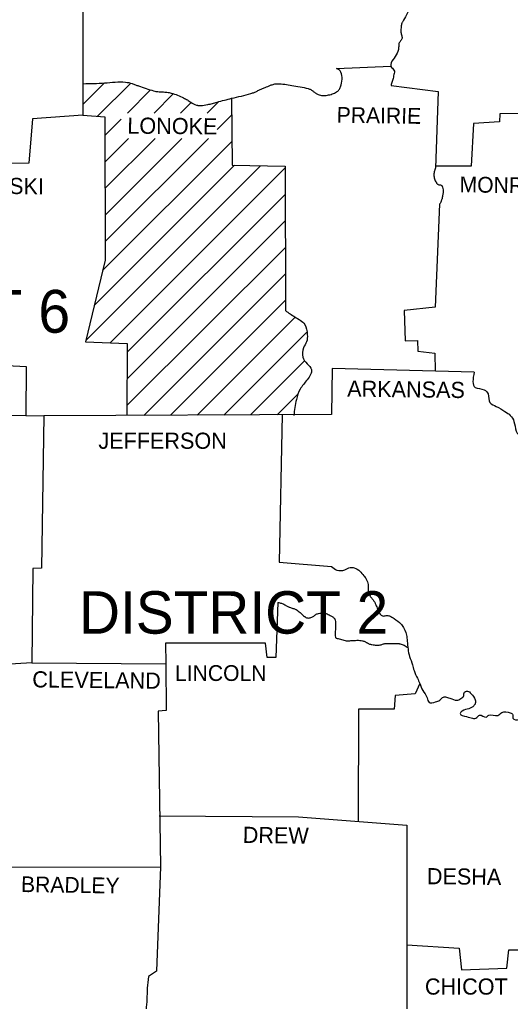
# Model space of a CAD drawing. Extents: x 1373878 to 1386598, y 1168333 to 1170533.
# Drawn here: x 1376588.9 to 1376719.5, y 1169816.7 to 1170078.1 of the extents above; entities that cross this region are included whole.
import ezdxf

# ---------------------------------------------------------------- set-up
doc = ezdxf.new("R2010")
doc.units = 0
for name, color, linetype in [('1', 7, 'Continuous'), ('Default', 7, 'Continuous'), ('R_Draft', 7, 'Continuous')]:
    doc.layers.add(name, color=color, linetype=linetype)

msp = doc.modelspace()

# ---------------------------------------------------------------- linework, layer by layer
at = {"layer": '1'}
for points in [[(1376599.19, 1170281.6), (1376599.39, 1170257.2), (1376597.69, 1170257.1), (1376597.99, 1170232.2), (1376590.99, 1170231.2), (1376591.59, 1170224.5), (1376593.99, 1170221.4), (1376593.79, 1170213.5), (1376580.19, 1170213), (1376579.69, 1170200.8), (1376567.29, 1170200.4), (1376566.69, 1170185.61), (1376567.39, 1170184.41), (1376567.69, 1170160.81), (1376589.09, 1170159.41), (1376588.79, 1170106.71), (1376605.79, 1170106.21), (1376605.79, 1170052.61), (1376592.39, 1170051.61), (1376591.39, 1170039.81), (1376568.89, 1170039.71)], [(1376673.29, 1170065.01), (1376687.68, 1170065.7)], [(1376687.79, 1170060.51), (1376700.29, 1170058.91), (1376699.59, 1170038.51)], [(1376700.69, 1170028.91), (1376699.49, 1170001.51), (1376691.29, 1170000.61), (1376691.49, 1169992.51), (1376694.79, 1169992.61), (1376694.89, 1169989.81), (1376699.39, 1169989.31), (1376699.54, 1169984.48)], [(1376709.89, 1169984.21), (1376672.09, 1169985.21), (1376671.89, 1169972.91), (1376595.39, 1169972.61)], [(1376537.79, 1169959.41), (1376543.39, 1169960.21), (1376543.79, 1169963.61), (1376547.09, 1169964.21), (1376547.29, 1169966.21), (1376570.59, 1169966.91), (1376571.49, 1169973.01), (1376595.39, 1169972.61)], [(1376592.19, 1169906.81), (1376577.57, 1169905.91)], [(1376592.19, 1169906.81), (1376627.82, 1169906.61)], [(1376627.82, 1169906.61), (1376627.89, 1169894.11), (1376625.79, 1169894.01), (1376626.39, 1169852.51)], [(1376626.39, 1169852.51), (1376625.39, 1169824.71), (1376623.19, 1169823.31)]]:
    msp.add_lwpolyline(points, dxfattribs=at)
for points in [[(1376700.49, 1170119.51), (1376700.43, 1170118.68), (1376700.36, 1170117.85), (1376700.22, 1170117.02), (1376700.12, 1170116.61), (1376700.06, 1170116.41), (1376699.99, 1170116.21), (1376699.67, 1170115.84), (1376699.16, 1170115.66), (1376698.59, 1170115.53), (1376698.32, 1170115.44), (1376698.09, 1170115.31), (1376696.92, 1170114.28), (1376695.89, 1170113.11), (1376695.7, 1170112.64), (1376695.66, 1170112.09), (1376695.6, 1170111.56), (1376695.39, 1170111.11), (1376695.21, 1170110.95), (1376695, 1170110.84), (1376694.51, 1170110.7), (1376694.01, 1170110.56), (1376693.59, 1170110.31), (1376693.12, 1170109.83), (1376692.67, 1170109.33), (1376692.26, 1170108.79), (1376691.89, 1170108.21), (1376691.21, 1170106.79), (1376690.79, 1170105.31), (1376690.71, 1170103.81), (1376690.79, 1170102.31), (1376690.86, 1170101.44), (1376690.98, 1170100.59), (1376691.18, 1170099.74), (1376691.32, 1170099.32), (1376691.49, 1170098.91), (1376691.96, 1170098.51), (1376692.65, 1170098.39), (1376693.39, 1170098.31), (1376693.99, 1170098.01), (1376694.19, 1170097.78), (1376694.38, 1170097.55), (1376694.7, 1170097.05), (1376695.19, 1170096.01), (1376695.22, 1170095.49), (1376695.07, 1170094.94), (1376694.94, 1170094.4), (1376694.99, 1170093.91), (1376695.46, 1170093.47), (1376696.15, 1170093.23), (1376696.86, 1170092.98), (1376697.39, 1170092.51), (1376697.57, 1170092.21), (1376697.72, 1170091.91), (1376697.81, 1170091.61), (1376697.79, 1170091.31), (1376697.39, 1170090.01), (1376696.29, 1170086.31), (1376696.22, 1170085.69), (1376696.27, 1170085.07), (1376696.35, 1170084.44), (1376696.39, 1170083.81), (1376696.35, 1170083.25), (1376696.29, 1170082.98), (1376696.19, 1170082.71), (1376695.67, 1170082.33), (1376694.87, 1170082.32), (1376694.06, 1170082.33), (1376693.49, 1170082.01), (1376691.89, 1170079.31), (1376690.79, 1170077.41), (1376690.66, 1170077.1), (1376690.45, 1170076.16), (1376690.41, 1170075.54), (1376690.39, 1170074.91), (1376690.44, 1170074.46), (1376690.57, 1170074.01), (1376690.68, 1170073.56), (1376690.69, 1170073.11), (1376690.55, 1170072.74), (1376690.32, 1170072.4), (1376690.07, 1170072.06), (1376689.89, 1170071.71), (1376689.81, 1170071.19), (1376689.8, 1170070.65), (1376689.75, 1170070.11), (1376689.59, 1170069.61), (1376688.59, 1170067.81), (1376687.69, 1170066.11), (1376687.73, 1170065.62), (1376688.12, 1170065.12), (1376688.55, 1170064.62), (1376688.69, 1170064.11), (1376688.55, 1170063.42), (1376688.39, 1170062.71), (1376688.24, 1170062.15), (1376688.06, 1170061.6), (1376687.79, 1170060.51)], [(1376605.79, 1170061), (1376611.59, 1170061.21), (1376617.09, 1170061.41), (1376618.86, 1170061.06), (1376619.73, 1170060.72), (1376620.16, 1170060.56), (1376620.59, 1170060.41), (1376624.59, 1170059.11), (1376625.17, 1170058.97), (1376625.75, 1170058.89), (1376626.94, 1170058.81), (1376628.13, 1170058.73), (1376629.29, 1170058.51), (1376632.59, 1170057.21), (1376633.09, 1170056.96), (1376633.57, 1170056.68), (1376634.52, 1170056.05), (1376635.98, 1170055.31), (1376636.23, 1170055.25), (1376636.49, 1170055.21), (1376637.11, 1170055.18), (1376638.99, 1170055.44), (1376640.25, 1170055.77), (1376641.49, 1170056.11), (1376645.39, 1170057.11), (1376650.49, 1170058.41), (1376651.34, 1170058.69), (1376652.16, 1170059.05), (1376652.97, 1170059.45), (1376653.79, 1170059.81), (1376654.26, 1170060), (1376655.67, 1170060.58), (1376656.62, 1170060.87), (1376657.11, 1170060.97), (1376657.59, 1170061.01), (1376659.49, 1170060.85), (1376661.39, 1170060.51), (1376663.55, 1170060.13), (1376665.69, 1170059.71), (1376666.42, 1170059.42), (1376667.08, 1170058.96), (1376667.73, 1170058.47), (1376668.39, 1170058.11), (1376669.56, 1170057.87), (1376670.84, 1170057.94), (1376672.12, 1170058.27), (1376672.73, 1170058.52), (1376673.29, 1170058.81), (1376673.9, 1170059.36), (1376674.35, 1170060.18), (1376674.74, 1170062.2), (1376674.41, 1170064.08), (1376673.96, 1170064.71), (1376673.29, 1170065.01)], [(1376699.59, 1170038.51), (1376699.48, 1170038.26), (1376699.39, 1170038.02), (1376699.26, 1170037.51), (1376699.2, 1170037.01), (1376699.19, 1170036.76), (1376699.19, 1170036.51), (1376699.27, 1170035.97), (1376699.44, 1170035.44), (1376699.69, 1170034.92), (1376699.84, 1170034.66), (1376699.99, 1170034.41), (1376700.13, 1170034.27), (1376700.31, 1170034.17), (1376700.73, 1170034.07), (1376701.13, 1170033.97), (1376701.28, 1170033.86), (1376701.35, 1170033.79), (1376701.39, 1170033.71), (1376701.44, 1170033.59), (1376701.49, 1170033.46), (1376701.64, 1170032.71), (1376701.65, 1170032.21), (1376701.63, 1170031.96), (1376701.59, 1170031.71), (1376701.4, 1170030.7), (1376701.27, 1170030.2), (1376701.19, 1170029.96), (1376701.09, 1170029.71), (1376700.91, 1170029.3), (1376700.69, 1170028.91)], [(1376709.89, 1169984.21), (1376710.19, 1169980.11), (1376712.59, 1169979.51), (1376713.59, 1169978.41), (1376714.09, 1169976.11), (1376715.79, 1169975.11), (1376718.09, 1169973.71), (1376719.49, 1169972.71), (1376720.49, 1169971.11), (1376721.09, 1169968.51), (1376722.69, 1169966.81), (1376724.89, 1169966.01), (1376726.49, 1169964.11), (1376727.49, 1169961.41), (1376729.09, 1169960.21), (1376730.69, 1169958.11), (1376731.49, 1169957.21), (1376732.89, 1169954.81), (1376734.29, 1169953.61), (1376735.29, 1169952.91), (1376736.89, 1169952.41), (1376738.89, 1169951.11), (1376740.19, 1169949.11), (1376740.19, 1169947.61), (1376739.69, 1169945.31), (1376739.29, 1169942.91), (1376739.09, 1169940.21), (1376738.89, 1169937.81), (1376739.79, 1169935.81), (1376739.29, 1169932.81), (1376738.29, 1169931.21), (1376738.19, 1169929.01), (1376737.89, 1169925.71), (1376737.49, 1169923.81), (1376736.59, 1169920.71), (1376735.29, 1169919.11)], [(1376623.19, 1169823.31), (1376622.89, 1169820.21), (1376622.79, 1169817.31), (1376622.59, 1169814.51), (1376622.54, 1169813.46), (1376622.54, 1169812.94), (1376622.59, 1169812.41), (1376622.79, 1169811.81), (1376623.14, 1169811.25), (1376623.51, 1169810.7), (1376623.79, 1169810.11), (1376624.49, 1169807.91), (1376625.19, 1169806.01), (1376626.59, 1169803.51), (1376626.9, 1169803.03), (1376627.24, 1169802.57), (1376627.58, 1169802.1), (1376627.89, 1169801.61), (1376628.4, 1169800.27), (1376628.45, 1169799.57), (1376628.29, 1169798.91), (1376627.49, 1169797.51), (1376627.13, 1169796.98), (1376626.74, 1169796.46), (1376626.35, 1169795.94), (1376625.99, 1169795.41), (1376625.83, 1169794.5), (1376626.04, 1169793.46), (1376626.21, 1169792.44), (1376625.89, 1169791.61), (1376625.69, 1169791.43), (1376625.47, 1169791.28), (1376625, 1169791), (1376624.53, 1169790.72), (1376624.09, 1169790.41), (1376622.96, 1169789.4), (1376622.39, 1169788.89), (1376621.79, 1169788.41), (1376620.49, 1169787.51), (1376619.09, 1169786.61), (1376618.68, 1169786.26), (1376618.32, 1169785.84), (1376617.97, 1169785.41), (1376617.59, 1169785.01), (1376617.06, 1169784.62), (1376616.48, 1169784.29), (1376615.9, 1169783.94), (1376615.39, 1169783.52), (1376614.95, 1169782.93), (1376614.58, 1169782.28), (1376614.21, 1169781.63), (1376613.79, 1169781.02), (1376613.38, 1169780.51), (1376612.95, 1169780.01), (1376611.99, 1169779.12), (1376610.49, 1169778.12), (1376609.97, 1169777.8), (1376609.44, 1169777.49), (1376608.65, 1169777), (1376608.39, 1169776.82), (1376608.03, 1169776.41), (1376607.8, 1169775.91), (1376607.49, 1169774.82), (1376607.23, 1169773.89), (1376606.99, 1169772.97), (1376606.83, 1169772.05), (1376606.79, 1169771.12), (1376606.92, 1169769.76), (1376607.09, 1169768.42), (1376607.49, 1169766.02), (1376607.45, 1169765.27), (1376607.24, 1169764.52), (1376607.04, 1169763.77), (1376606.99, 1169763.02), (1376607.49, 1169759.72), (1376607.99, 1169757.12), (1376608.79, 1169754.82), (1376609.89, 1169752.22), (1376610.55, 1169750.99), (1376611.29, 1169749.82), (1376612.55, 1169748.11), (1376613.93, 1169746.5)]]:
    msp.add_spline(points, degree=3, dxfattribs=at)
at = {"layer": 'Default'}
for points in [[(1376738.99, 1170107.91), (1376740.49, 1170053.11), (1376716.69, 1170053.01), (1376716.59, 1170050.81), (1376709.69, 1170050.41), (1376709.09, 1170039.01), (1376699.61, 1170039.01)], [(1376645.29, 1170057.21), (1376645.49, 1170039.31), (1376659.59, 1170039.01), (1376659.69, 1170000.61)], [(1376605.79, 1170052.61), (1376611.59, 1170052.21), (1376611.69, 1170014.01), (1376606.49, 1169992.31), (1376617.59, 1169991.81), (1376617.49, 1169972.7)], [(1376527.89, 1170027.65), (1376539.79, 1170026.91), (1376539.39, 1170014.41), (1376552.49, 1170013.91), (1376552.69, 1170003.01), (1376558.89, 1170002.51), (1376558.89, 1170000.61), (1376564.69, 1170000.21), (1376564.89, 1169993.21), (1376578.09, 1169993.21), (1376578.49, 1169986.31), (1376590.69, 1169985.71), (1376590.59, 1169972.69)], [(1376595.39, 1169972.61), (1376594.79, 1169932.01), (1376592.49, 1169931.91), (1376592.19, 1169906.81)], [(1376658.83, 1169972.86), (1376657.99, 1169933.61), (1376671.89, 1169932.51)], [(1376657.69, 1169922.91), (1376657.09, 1169908.21), (1376654.79, 1169908.21), (1376654.39, 1169912.11), (1376627.79, 1169912.11), (1376627.82, 1169906.61)], [(1376695.39, 1169901.31), (1376694.19, 1169898.61), (1376688.89, 1169898.11), (1376688.59, 1169894.51), (1376679.09, 1169894.51), (1376678.99, 1169864.61)], [(1376626.09, 1169866.11), (1376663.19, 1169865.81), (1376691.99, 1169863.61)], [(1376691.99, 1169863.61), (1376691.99, 1169803.81), (1376692.79, 1169746.38)], [(1376581.19, 1169852.41), (1376626.39, 1169852.51)], [(1376691.99, 1169831.74), (1376705.89, 1169830.91), (1376706.49, 1169825.11), (1376718.59, 1169825.51), (1376719.09, 1169830.41), (1376722.83, 1169830.41)]]:
    msp.add_lwpolyline(points, dxfattribs=at)
for points in [[(1376659.69, 1170000.61), (1376662.19, 1169998.91), (1376664.79, 1169996.91), (1376665.49, 1169994.21), (1376665.29, 1169992.31), (1376664.49, 1169990.71), (1376664.29, 1169988.21), (1376665.49, 1169986.41), (1376666.59, 1169984.91), (1376665.49, 1169982.21), (1376663.59, 1169979.71), (1376662.59, 1169976.91), (1376661.89, 1169972.71)], [(1376671.89, 1169932.51), (1376673.39, 1169931.51), (1376675.49, 1169931.61), (1376676.89, 1169932.21), (1376677.99, 1169932.11), (1376679.49, 1169931.21), (1376680.49, 1169930.01), (1376681.19, 1169929.11), (1376681.69, 1169927.71), (1376681.69, 1169926.41), (1376682.19, 1169924.61), (1376682.79, 1169923.91), (1376683.59, 1169922.61), (1376684.09, 1169921.41), (1376684.39, 1169920.61), (1376685.49, 1169919.31), (1376686.49, 1169919.41), (1376687.39, 1169919.31), (1376688.59, 1169918.61), (1376690.39, 1169917.21), (1376690.69, 1169916.81), (1376691.89, 1169914.21), (1376692.09, 1169912.61), (1376692.29, 1169910.51), (1376692.69, 1169908.51), (1376693.49, 1169906.31), (1376693.89, 1169904.81), (1376694.79, 1169902.71), (1376695.39, 1169901.31), (1376696.19, 1169899.51), (1376697.39, 1169897.51), (1376697.89, 1169896.31), (1376699.59, 1169896.41), (1376700.79, 1169896.91), (1376701.69, 1169897.71), (1376702.79, 1169897.61), (1376703.99, 1169897.21), (1376705.59, 1169896.91), (1376706.59, 1169897.51), (1376707.09, 1169897.91), (1376707.19, 1169898.81), (1376708.09, 1169899.31), (1376709.09, 1169898.61), (1376710.19, 1169897.01), (1376710.19, 1169896.01), (1376709.79, 1169895.41), (1376708.49, 1169894.61), (1376706.69, 1169894.01), (1376706.19, 1169893.31), (1376707.89, 1169892.51), (1376710.59, 1169892.31), (1376711.29, 1169892.91), (1376713.09, 1169892.41), (1376713.79, 1169892.91), (1376716.19, 1169892.81), (1376717.29, 1169893.61), (1376719.49, 1169893.51), (1376720.19, 1169893.01), (1376720.19, 1169892.11), (1376721.99, 1169891.71), (1376723.29, 1169892.01), (1376724.99, 1169891.51), (1376726.49, 1169890.71), (1376727.29, 1169889.61), (1376728.29, 1169888.41), (1376729.19, 1169888.71), (1376729.89, 1169889.61), (1376731.39, 1169891.21), (1376731.39, 1169892.21), (1376731.79, 1169892.91), (1376732.39, 1169894.21)], [(1376657.69, 1169922.91), (1376658.16, 1169922.81), (1376658.61, 1169922.68), (1376659.49, 1169922.31), (1376659.82, 1169922.14), (1376660.15, 1169921.96), (1376660.47, 1169921.78), (1376660.79, 1169921.61), (1376661.21, 1169921.45), (1376661.65, 1169921.33), (1376662.08, 1169921.2), (1376662.49, 1169921.01), (1376663.06, 1169920.63), (1376663.59, 1169920.21), (1376663.97, 1169919.89), (1376664.34, 1169919.55), (1376664.7, 1169919.21), (1376664.89, 1169919.06), (1376665.09, 1169918.91), (1376665.51, 1169918.77), (1376665.97, 1169918.8), (1376666.45, 1169918.93), (1376666.89, 1169919.11), (1376667.22, 1169919.3), (1376667.53, 1169919.53), (1376667.84, 1169919.75), (1376668.19, 1169919.91), (1376669.49, 1169920.11), (1376670.49, 1169920.01), (1376671.59, 1169919.41), (1376672.25, 1169919.04), (1376672.54, 1169918.82), (1376672.68, 1169918.68), (1376672.74, 1169918.6), (1376672.79, 1169918.51), (1376672.99, 1169917.87), (1376673, 1169917.54), (1376672.99, 1169917.21), (1376672.99, 1169915.71), (1376672.99, 1169913.61), (1376673.07, 1169913.47), (1376673.25, 1169913.39), (1376673.69, 1169913.31), (1376674.93, 1169912.93), (1376676.19, 1169912.71), (1376676.62, 1169912.72), (1376677.04, 1169912.75), (1376677.47, 1169912.79), (1376677.89, 1169912.81), (1376678.69, 1169912.83), (1376679.49, 1169912.81), (1376680.15, 1169912.71), (1376680.47, 1169912.62), (1376680.79, 1169912.51), (1376681.08, 1169912.37), (1376681.34, 1169912.2), (1376681.61, 1169912.04), (1376681.89, 1169911.91), (1376682.69, 1169911.71), (1376683.89, 1169911.51), (1376684.89, 1169911.61), (1376685.32, 1169911.72), (1376685.74, 1169911.85), (1376686.16, 1169911.96), (1376686.59, 1169912.01), (1376687.59, 1169912.01), (1376689.19, 1169912.01), (1376689.69, 1169911.98), (1376689.94, 1169911.95), (1376690.19, 1169911.91), (1376691.26, 1169911.51), (1376691.77, 1169911.21), (1376692.25, 1169910.88)]]:
    msp.add_spline(points, degree=3, dxfattribs=at)
at = {"layer": 'R_Draft'}
for p, q in [((1376605.79, 1170055.51), (1376611.48, 1170061.2)), ((1376609.69, 1170052.33), (1376618.52, 1170061.17)), ((1376617.63, 1170053.2), (1376623.78, 1170059.36)), ((1376624.7, 1170053.2), (1376629.83, 1170058.33)), ((1376631.77, 1170053.2), (1376634.58, 1170056.01)), ((1376638.84, 1170053.2), (1376641.83, 1170056.19)), ((1376611.61, 1170047.18), (1376615.99, 1170051.56)), ((1376641.53, 1170048.82), (1376645.34, 1170052.63)), ((1376611.62, 1170040.13), (1376617.95, 1170046.45)), ((1376611.64, 1170033.07), (1376625.02, 1170046.45)), ((1376611.66, 1170026.02), (1376632.09, 1170046.45)), ((1376611.68, 1170018.97), (1376639.16, 1170046.45)), ((1376611.03, 1170011.25), (1376645.42, 1170045.64)), ((1376606.58, 1169992.65), (1376653.07, 1170039.14)), ((1376608.81, 1170001.95), (1376646.14, 1170039.29)), ((1376613, 1169992.01), (1376659.59, 1170038.6)), ((1376617.58, 1169989.51), (1376659.61, 1170031.55)), ((1376617.54, 1169982.41), (1376659.63, 1170024.49)), ((1376617.5, 1169975.3), (1376659.65, 1170017.44)), ((1376621.99, 1169972.71), (1376659.67, 1170010.39)), ((1376629.09, 1169972.73), (1376659.69, 1170003.34)), ((1376636.18, 1169972.76), (1376662.27, 1169998.85)), ((1376643.28, 1169972.79), (1376665.46, 1169994.97)), ((1376650.38, 1169972.82), (1376664.87, 1169987.3)), ((1376657.48, 1169972.85), (1376663.01, 1169978.37))]:
    msp.add_line(p, q, dxfattribs=at)

# ---------------------------------------------------------------- texts
at = {"layer": 'Default'}
for s, height, rotation, p in [('PRAIRIE', 4.2, 359.2116, (1376673.29, 1170050.61)), ('LONOKE', 4.301, 359.4974, (1376617.59, 1170047.71)), ('PULASKI', 4.301, 359.0531, (1376571.09, 1170031.91)), ('MONROE', 4.199, 359.0331, (1376705.99, 1170032.11)), ('ARKANSAS', 4.299, 359.2678, (1376676.09, 1169977.71)), ('CLEVELAND', 4.301, 359.3377, (1376592.29, 1169900.31)), ('DREW', 4.299, 359.2258, (1376648.29, 1169858.91)), ('BRADLEY', 4.199, 359.1449, (1376589.29, 1169845.81)), ('DESHA', 4.299, 359.3704, (1376697.29, 1169847.91))]:
    msp.add_text(s, height=height, rotation=rotation, dxfattribs=at).set_placement(p)
for s, height, p in [('DISTRICT 6', 11.4, (1376519.39, 1169994.71)), ('JEFFERSON', 4.3, (1376609.89, 1169963.81)), ('DISTRICT 2', 11.299, (1376604.74, 1169914.6)), ('LINCOLN', 4.2, (1376630.29, 1169902.01)), ('CHICOT', 4.3, (1376696.79, 1169818.51))]:
    msp.add_text(s, height=height, dxfattribs=at).set_placement(p)

doc.saveas('drawing.dxf')
